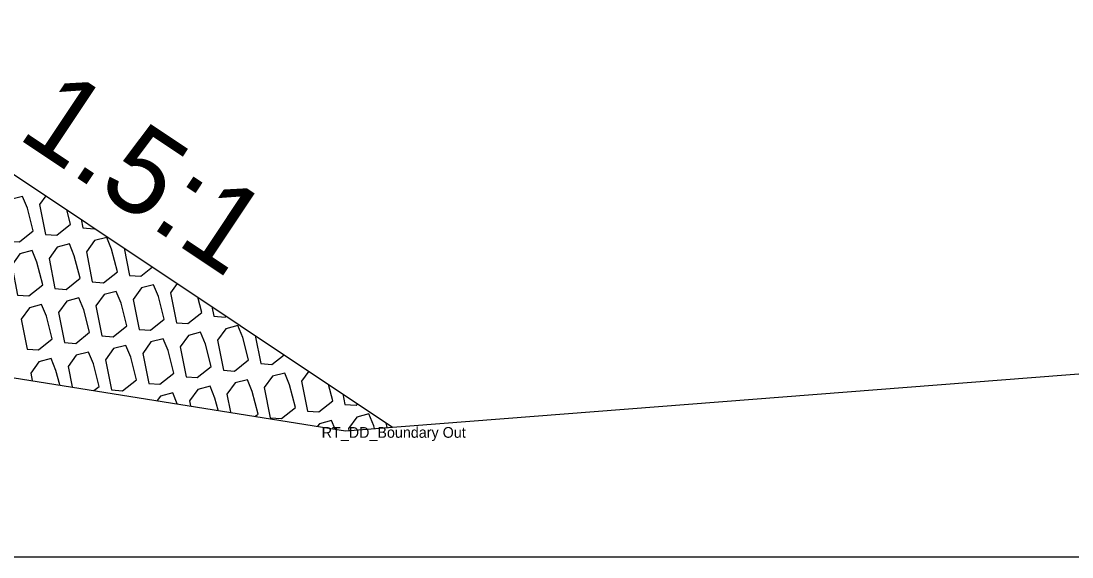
# Model space of a CAD drawing. Extents: x -26 to 203, y -10 to 20020.
# Drawn here: x 130.56 to 140.37, y 2000 to 2005 of the extents above; entities that cross this region are included whole.
import ezdxf

# ---------------------------------------------------------------- set-up
doc = ezdxf.new("R2010")
doc.units = 0
for name, color, linetype in [('Default', 7, 'Continuous'), ('Exist Cross Section Cell', 7, 'Continuous'), ('Exist XS Ground Line', 7, 'Continuous'), ('Old_Level_1', 7, 'Continuous'), ('Prop CMT Rip Rap Class II', 7, 'Continuous'), ('Prop XS Side Slope Text', 7, 'Continuous')]:
    doc.layers.add(name, color=color, linetype=linetype)

msp = doc.modelspace()

# ---------------------------------------------------------------- linework, layer by layer
at = {"layer": 'Exist Cross Section Cell'}
msp.add_line((100, 2000), (200, 2000), dxfattribs=at)
at = {"layer": 'Exist XS Ground Line'}
for p, q in [((126.0976, 2002.376), (133.5908, 2001.1779)), ((133.5908, 2001.1779), (144.7656, 2002.0466))]:
    msp.add_line(p, q, dxfattribs=at)
at = {"layer": 'Old_Level_1'}
for p, q in [((131.1222, 2003.1501), (131.1381, 2003.07)), ((131.5252, 2002.8815), (131.5756, 2002.6274)), ((132.344, 2002.3356), (132.3617, 2002.2462)), ((132.7469, 2002.067), (132.7992, 2001.8036)), ((133.5657, 2001.5211), (133.5853, 2001.4225)), ((133.9686, 2001.2524), (133.9774, 2001.208))]:
    msp.add_line(p, q, dxfattribs=at)
for points in [[(130.441, 2002.947), (130.5462, 2002.9394), (130.6758, 2003.0426), (130.6213, 2003.2532), (130.5762, 2003.3629), (130.4624, 2003.3335), (130.3853, 2003.227)], [(131.227, 2002.5659), (131.3323, 2002.5583), (131.4618, 2002.6615), (131.4074, 2002.872), (131.3622, 2002.9817), (131.2485, 2002.9523), (131.1714, 2002.8459)], [(130.5298, 2002.443), (130.6351, 2002.4353), (130.7646, 2002.5385), (130.7102, 2002.7491), (130.665, 2002.8588), (130.5513, 2002.8294), (130.4742, 2002.723)], [(130.8784, 2002.5044), (130.9837, 2002.4968), (131.1132, 2002.6), (131.0588, 2002.8106), (131.0136, 2002.9203), (130.8999, 2002.8909), (130.8228, 2002.7844)], [(131.6645, 2002.1233), (131.7698, 2002.1157), (131.8993, 2002.2189), (131.8449, 2002.4294), (131.7997, 2002.5391), (131.686, 2002.5097), (131.6089, 2002.4033)], [(131.3159, 2002.0618), (131.4212, 2002.0542), (131.5507, 2002.1574), (131.4963, 2002.368), (131.4511, 2002.4777), (131.3374, 2002.4483), (131.2603, 2002.3418)], [(130.6187, 2001.9389), (130.724, 2001.9313), (130.8535, 2002.0345), (130.7991, 2002.245), (130.7539, 2002.3547), (130.6402, 2002.3253), (130.5631, 2002.2189)], [(130.9673, 2002.0004), (131.0726, 2001.9927), (131.2021, 2002.0959), (131.1477, 2002.3065), (131.1025, 2002.4162), (130.9888, 2002.3868), (130.9117, 2002.2804)], [(132.4506, 2001.7422), (132.5558, 2001.7345), (132.6854, 2001.8377), (132.6309, 2002.0483), (132.5858, 2002.158), (132.472, 2002.1286), (132.395, 2002.0222)], [(132.102, 2001.6807), (132.2072, 2001.673), (132.3368, 2001.7763), (132.2823, 2001.9868), (132.2372, 2002.0965), (132.1234, 2002.0671), (132.0464, 2001.9607)], [(131.4048, 2001.5578), (131.5101, 2001.5501), (131.6396, 2001.6533), (131.5851, 2001.8639), (131.54, 2001.9736), (131.4262, 2001.9442), (131.3492, 2001.8378)], [(131.7534, 2001.6192), (131.8587, 2001.6116), (131.9882, 2001.7148), (131.9337, 2001.9254), (131.8886, 2002.0351), (131.7748, 2002.0056), (131.6978, 2001.8992)], [(132.8881, 2001.2996), (132.9933, 2001.2919), (133.1229, 2001.3951), (133.0684, 2001.6057), (133.0233, 2001.7154), (132.9095, 2001.686), (132.8324, 2001.5796)]]:
    msp.add_lwpolyline(points, close=True, dxfattribs=at)
for points in [[(130.7928, 2003.3698), (130.7339, 2003.2885), (130.7896, 2003.0085)], [(130.7896, 2003.0085), (130.8948, 2003.0009), (131.0244, 2003.1041), (130.9896, 2003.2385)], [(131.1381, 2003.07), (131.2434, 2003.0623), (131.2482, 2003.0661)], [(131.5756, 2002.6274), (131.6809, 2002.6197), (131.7888, 2002.7057)], [(132.0202, 2002.5514), (131.9575, 2002.4648), (132.0131, 2002.1848)], [(132.0131, 2002.1848), (132.1184, 2002.1771), (132.2479, 2002.2803), (132.2106, 2002.4245)], [(132.3617, 2002.2462), (132.467, 2002.2386), (132.4772, 2002.2467)], [(130.9233, 2001.6044), (130.888, 2001.741), (130.8428, 2001.8507), (130.7291, 2001.8212), (130.652, 2001.7148), (130.6657, 2001.6456)], [(131.2427, 2001.5534), (131.291, 2001.5919), (131.2366, 2001.8024), (131.1914, 2001.9121), (131.0776, 2001.8827), (131.0006, 2001.7763), (131.0384, 2001.586)], [(132.7992, 2001.8036), (132.9044, 2001.796), (133.0178, 2001.8863)], [(132.7479, 2001.3127), (132.7743, 2001.3337), (132.7198, 2001.5442), (132.6747, 2001.6539), (132.5609, 2001.6245), (132.4839, 2001.5181), (132.5173, 2001.3496)], [(133.2477, 2001.7331), (133.181, 2001.641), (133.2367, 2001.361)], [(132.4008, 2001.3682), (132.3712, 2001.4828), (132.3261, 2001.5925), (132.2123, 2001.563), (132.1353, 2001.4566), (132.1447, 2001.4091)], [(133.2367, 2001.361), (133.3419, 2001.3534), (133.4715, 2001.4566), (133.4317, 2001.6104)], [(132.0194, 2001.4292), (131.9775, 2001.531), (131.8637, 2001.5016), (131.8329, 2001.459)], [(133.5853, 2001.4225), (133.6905, 2001.4148), (133.7062, 2001.4274)], [(133.4934, 2001.1935), (133.4607, 2001.2728), (133.347, 2001.2434), (133.3298, 2001.2197)], [(133.8611, 2001.1989), (133.8545, 2001.2246), (133.8093, 2001.3343), (133.6956, 2001.3048), (133.6185, 2001.1984), (133.6221, 2001.1804)]]:
    msp.add_lwpolyline(points, dxfattribs=at)
at = {"layer": 'Prop CMT Rip Rap Class II'}
msp.add_lwpolyline([(119.5838, 2005), (128.3475, 2005), (134.0292, 2001.212)], dxfattribs=at)

# ---------------------------------------------------------------- texts
at = {"layer": 'Default'}
msp.add_text('RT_DD_Boundary Out', height=0.1, dxfattribs=at).set_placement((133.368, 2001.112))
at = {"layer": 'Prop XS Side Slope Text'}
msp.add_text('1.5:1', height=0.8, rotation=326.30861, dxfattribs=at).set_placement((130.5121, 2003.9175))

doc.saveas('drawing.dxf')
